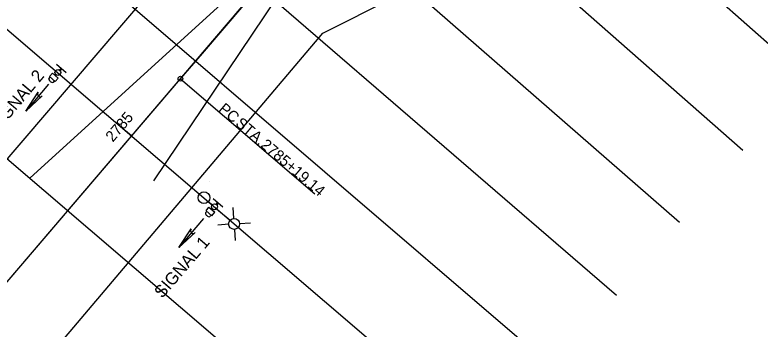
# Model space of a CAD drawing. Extents: x 2376379 to 2383101, y 559608 to 561720.
# Drawn here: x 2376777.4 to 2376967, y 560941 to 561020.9 of the extents above; entities that cross this region are included whole.
import ezdxf

# ---------------------------------------------------------------- set-up
doc = ezdxf.new("R2010")
doc.units = 0
for name, color, linetype in [('BR_X_SV_Bottom_of_Beam', 7, 'Continuous'), ('BR_X_SV_Pier', 7, 'Continuous'), ('DT_X_Contour_Minor', 7, 'Continuous'), ('HY_X_Spring_Cells', 7, 'Continuous'), ('PM_X_Surveyed_Line', 7, 'Continuous'), ('PV_X_COP', 7, 'Continuous'), ('PV_X_EOP', 7, 'Continuous'), ('RD_X_Cells', 7, 'Continuous'), ('TopoDOT_Transients', 7, 'Continuous')]:
    doc.layers.add(name, color=color, linetype=linetype)

msp = doc.modelspace()

# ---------------------------------------------------------------- linework, layer by layer
at = {"layer": 'BR_X_SV_Bottom_of_Beam'}
msp.add_line((2376781.2, 560979.35), (2376892.99, 561080.98), dxfattribs=at)
at = {"layer": 'BR_X_SV_Pier'}
for p, q in [((2376787.99, 561008.33), (2376790.48, 561006.25)), ((2376787.99, 561008.33), (2376790.48, 561006.25)), ((2376786.2, 561005.17), (2376786.94, 561006.05)), ((2376786.2, 561005.17), (2376786.94, 561006.05)), ((2376786.94, 561006.05), (2376788.43, 561004.81)), ((2376786.94, 561006.05), (2376788.43, 561004.81)), ((2376787.76, 561005.71), (2376787.59, 561005.51)), ((2376787.76, 561005.71), (2376787.59, 561005.51)), ((2376787.94, 561005.56), (2376787.77, 561005.35)), ((2376787.94, 561005.56), (2376787.77, 561005.35)), ((2376789.14, 561007.37), (2376788.72, 561006.86)), ((2376789.14, 561007.37), (2376788.72, 561006.86)), ((2376789.33, 561007.21), (2376788.9, 561006.7)), ((2376789.33, 561007.21), (2376788.9, 561006.7)), ((2376786.08, 561004.64), (2376786.39, 561005.01)), ((2376786.08, 561004.64), (2376786.39, 561005.01)), ((2376786.2, 561005.17), (2376787.69, 561003.93)), ((2376786.2, 561005.17), (2376787.69, 561003.93)), ((2376787.19, 561003.71), (2376787.5, 561004.08)), ((2376787.19, 561003.71), (2376787.5, 561004.08)), ((2376787.69, 561003.93), (2376788.43, 561004.81)), ((2376787.69, 561003.93), (2376788.43, 561004.81)), ((2376785.96, 561003.28), (2376780.21, 560996.42)), ((2376780.21, 560996.42), (2376783.29, 561001.18)), ((2376784.37, 561000.28), (2376780.21, 560996.42)), ((2376826.64, 560973.4), (2376827.6, 560972.57)), ((2376827.85, 560974.2), (2376830.32, 560972.1)), ((2376826.03, 560971.07), (2376826.77, 560971.94)), ((2376826.77, 560971.94), (2376828.25, 560970.68)), ((2376827.59, 560971.59), (2376827.42, 560971.39)), ((2376827.59, 560971.59), (2376827.42, 560971.39)), ((2376827.78, 560971.43), (2376827.6, 560971.23)), ((2376827.78, 560971.43), (2376827.6, 560971.23)), ((2376828.99, 560973.23), (2376828.56, 560972.73)), ((2376828.99, 560973.23), (2376828.56, 560972.73)), ((2376828.74, 560971.58), (2376832.14, 560968.64)), ((2376829.17, 560973.07), (2376828.75, 560972.57)), ((2376829.17, 560973.07), (2376828.75, 560972.57)), ((2376833.09, 560969.11), (2376832.9, 560971.91)), ((2376825.9, 560970.53), (2376826.22, 560970.9)), ((2376825.9, 560970.53), (2376826.22, 560970.9)), ((2376826.03, 560971.07), (2376827.51, 560969.81)), ((2376827, 560969.6), (2376827.31, 560969.97)), ((2376827, 560969.6), (2376827.31, 560969.97)), ((2376827.51, 560969.81), (2376828.25, 560970.68)), ((2376825.39, 560969.06), (2376819.11, 560961.72)), ((2376831.8, 560967.62), (2376829, 560967.42)), ((2376834.59, 560967.82), (2376837.38, 560968.02)), ((2376819.11, 560961.72), (2376822.24, 560966.45)), ((2376833.29, 560966.32), (2376833.49, 560963.53)), ((2376823.3, 560965.54), (2376819.11, 560961.72))]:
    msp.add_line(p, q, dxfattribs=at)
for centre, radius in [((2376788.33, 561006.21), 0.757), ((2376788.33, 561006.21), 0.757), ((2376788.33, 561006.21), 0.757), ((2376788.33, 561006.21), 0.757), ((2376788.33, 561006.21), 0.757), ((2376788.33, 561006.21), 0.757), ((2376788.33, 561006.21), 0.757), ((2376788.33, 561006.21), 0.757), ((2376788.33, 561006.21), 0.757), ((2376788.33, 561006.21), 0.757), ((2376788.33, 561006.21), 0.757), ((2376788.33, 561006.21), 0.757), ((2376825.51, 560974.38), 1.5), ((2376828.17, 560972.08), 0.757), ((2376833.19, 560967.72), 1.4)]:
    msp.add_circle(centre, radius, dxfattribs=at)
for centre, radius, start, end in [((2376783.83, 561000.73), 0.702, 139.9991, 319.9991), ((2376822.77, 560965.99), 0.703, 139.4084, 319.4084)]:
    msp.add_arc(centre, radius, start, end, dxfattribs=at)
for centre, major_axis in [((2376786.63, 561004.18), (-0.553, 0.462)), ((2376786.63, 561004.18), (-0.553, 0.462)), ((2376826.45, 560970.07), (-0.548, 0.468)), ((2376826.45, 560970.07), (-0.548, 0.468))]:
    msp.add_ellipse(centre, major_axis=major_axis, ratio=0.45371, start_param=0, end_param=3.141593, dxfattribs=at)
at = {"layer": 'DT_X_Contour_Minor'}
for p, q in [((2376726.65, 560927.31), (2376823.82, 561040.67)), ((2376855.78, 561016.25), (2376878.27, 561027.54)), ((2376757.77, 560900.7), (2376855.78, 561016.25))]:
    msp.add_line(p, q, dxfattribs=at)
at = {"layer": 'HY_X_Spring_Cells'}
msp.add_line((2376819.53, 561004.64), (2376853.74, 560975.4), dxfattribs=at)
msp.add_circle((2376819.53, 561004.64), 0.6, dxfattribs=at)
at = {"layer": 'PM_X_Surveyed_Line'}
for p, q in [((2376978.82, 561004.82), (2376799.3, 561164.12)), ((2376782.41, 561144.99), (2376962.61, 560986.48)), ((2376946.49, 560968.06), (2376765.59, 561125.79)), ((2376748.86, 561106.51), (2376930.44, 560949.58)), ((2376914.48, 560931.03), (2376732.21, 561087.17)), ((2376715.88, 561068.07), (2376898.31, 560912.12)), ((2376699.64, 561049.07), (2376882.06, 560893.12))]:
    msp.add_line(p, q, dxfattribs=at)
at = {"layer": 'PV_X_COP'}
msp.add_line((2376812.75, 560978.69), (2376885.88, 561087.29), dxfattribs=at)
at = {"layer": 'PV_X_EOP'}
msp.add_line((2376807.1, 560990.1), (2376805.58, 560991.4), dxfattribs=at)
at = {"layer": 'RD_X_Cells'}
for q in [(2376995.66, 561210.67), (2376819.53, 561004.64)]:
    msp.add_line((2376415.94, 560532.55), q, dxfattribs=at)
msp.add_arc((2381174.86, 557281.31), 5729.93, 134.056462, 139.473129, dxfattribs=at)
msp.add_arc((2381174.86, 557281.31), 5729.93, 134.056462, 139.473129, dxfattribs=at)
at = {"layer": 'TopoDOT_Transients'}
msp.add_lwpolyline([(2376827, 560978.38), (2376827, 560978.38), (2376827, 560978.38)], close=True, dxfattribs=at)

# ---------------------------------------------------------------- texts
at = {"layer": 'BR_X_SV_Pier'}
for s, rotation, p in [('SIGNAL 2', 49.9991, (2376772.98, 560990.87)), ('SIGNAL 1', 49.4084, (2376814.92, 560948.62))]:
    msp.add_text(s, height=3.125, rotation=rotation, dxfattribs=at).set_placement(p)
at = {"layer": 'HY_X_Spring_Cells'}
for s, p in [('PC', (2376829.04, 560996.58)), (' STA. ', (2376832.52, 560993.6)), ('2785+19.14', (2376839.71, 560987.45))]:
    msp.add_text(s, height=2.8, rotation=319.4731, dxfattribs=at).set_placement(p)
at = {"layer": 'PV_X_EOP'}
msp.add_text('2785', height=2.8, rotation=49.4731, dxfattribs=at).set_placement((2376802.32, 560988.36))

doc.saveas('drawing.dxf')
